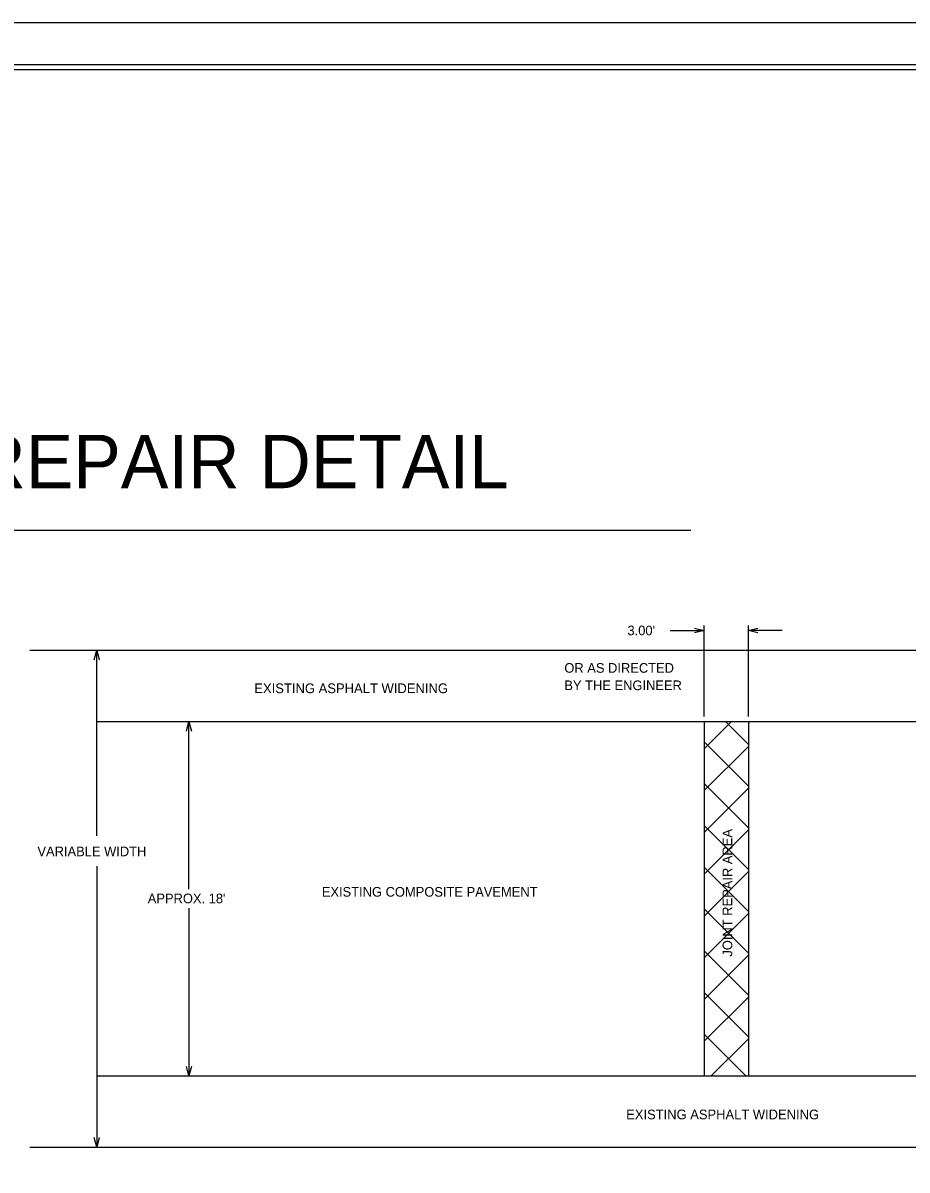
# Model space of a CAD drawing. Extents: x 2455709 to 2456046, y 594728 to 594947.
# Drawn here: x 2455864.9 to 2455949.3, y 594837 to 594946.6 of the extents above; entities that cross this region are included whole.
import ezdxf

# ---------------------------------------------------------------- set-up
doc = ezdxf.new("R2010")
doc.units = 0
for name, color, linetype in [('Default', 7, 'Continuous'), ('Old_Level_3', 7, 'Continuous'), ('Prop Horizontal Alignment', 7, 'Continuous'), ('Prop Roadway Culvert', 7, 'Continuous'), ('Prop Vertical Profile Grade', 7, 'Continuous')]:
    doc.layers.add(name, color=color, linetype=linetype)

msp = doc.modelspace()

# ---------------------------------------------------------------- linework, layer by layer
at = {"layer": 'Default'}
for p, q in [((2455830.77, 594898.13), (2455928.67, 594898.13)), ((2455830.77, 594898.13), (2455928.67, 594898.13)), ((2455929.93, 594880.31), (2455929.93, 594889)), ((2455929.93, 594880.31), (2455929.93, 594889)), ((2455934.16, 594880.31), (2455934.16, 594889)), ((2455934.16, 594880.31), (2455934.16, 594889)), ((2455926.7, 594888.54), (2455929.93, 594888.54)), ((2455926.7, 594888.54), (2455929.93, 594888.54)), ((2455937.39, 594888.54), (2455934.16, 594888.54)), ((2455937.39, 594888.54), (2455934.16, 594888.54)), ((2455865.51, 594886.65), (2455872.36, 594886.65)), ((2455865.51, 594886.65), (2455872.36, 594886.65)), ((2455871.9, 594870.64), (2455871.9, 594886.65)), ((2455871.9, 594868.91), (2455871.9, 594886.65)), ((2455871.9, 594886.65), (2455992.19, 594886.65)), ((2455871.9, 594879.85), (2455992.19, 594879.85)), ((2455871.9, 594879.85), (2455992.19, 594879.85)), ((2455871.9, 594879.85), (2455992.19, 594879.85)), ((2455871.9, 594879.85), (2455992.19, 594879.85)), ((2455871.9, 594879.85), (2455992.19, 594879.85)), ((2455871.9, 594879.85), (2455992.19, 594879.85)), ((2455871.9, 594879.85), (2455992.19, 594879.85)), ((2455871.9, 594879.85), (2455992.19, 594879.85)), ((2455871.9, 594879.85), (2455992.19, 594879.85)), ((2455874.32, 594879.85), (2455881.18, 594879.85)), ((2455874.32, 594879.85), (2455881.18, 594879.85)), ((2455880.72, 594863.84), (2455880.72, 594879.85)), ((2455880.72, 594863.84), (2455880.72, 594879.85)), ((2455929.93, 594879.85), (2455929.93, 594845.98)), ((2455929.93, 594877.23), (2455932.55, 594879.85)), ((2455929.93, 594879.85), (2455934.16, 594879.85)), ((2455929.93, 594879.85), (2455929.93, 594845.98)), ((2455929.93, 594877.23), (2455932.55, 594879.85)), ((2455929.93, 594879.85), (2455934.16, 594879.85)), ((2455931.97, 594879.85), (2455934.16, 594877.66)), ((2455931.97, 594879.85), (2455934.16, 594877.66)), ((2455934.16, 594879.85), (2455934.16, 594845.98)), ((2455934.16, 594879.85), (2455934.16, 594845.98)), ((2455929.93, 594877.91), (2455934.16, 594873.67)), ((2455929.93, 594877.91), (2455934.16, 594873.67)), ((2455929.93, 594873.24), (2455934.16, 594877.47)), ((2455929.93, 594873.24), (2455934.16, 594877.47)), ((2455929.93, 594873.92), (2455934.16, 594869.68)), ((2455929.93, 594873.92), (2455934.16, 594869.68)), ((2455929.93, 594869.25), (2455934.16, 594873.48)), ((2455929.93, 594869.25), (2455934.16, 594873.48)), ((2455929.93, 594869.92), (2455934.16, 594865.69)), ((2455929.93, 594869.92), (2455934.16, 594865.69)), ((2455929.93, 594865.25), (2455934.16, 594869.49)), ((2455929.93, 594865.25), (2455934.16, 594869.49)), ((2455871.9, 594866.01), (2455871.9, 594839.18)), ((2455929.93, 594865.93), (2455934.16, 594861.7)), ((2455929.93, 594865.93), (2455934.16, 594861.7)), ((2455929.93, 594861.26), (2455934.16, 594865.5)), ((2455929.93, 594861.26), (2455934.16, 594865.5)), ((2455871.9, 594862), (2455871.9, 594845.98)), ((2455880.72, 594862), (2455880.72, 594845.98)), ((2455880.72, 594862), (2455880.72, 594845.98)), ((2455929.93, 594861.94), (2455934.16, 594857.71)), ((2455929.93, 594861.94), (2455934.16, 594857.71)), ((2455929.93, 594857.27), (2455934.16, 594861.5)), ((2455929.93, 594857.27), (2455934.16, 594861.5)), ((2455929.93, 594857.95), (2455934.16, 594853.71)), ((2455929.93, 594857.95), (2455934.16, 594853.71)), ((2455929.93, 594853.28), (2455934.16, 594857.51)), ((2455929.93, 594853.28), (2455934.16, 594857.51)), ((2455929.93, 594853.96), (2455934.16, 594849.72)), ((2455929.93, 594853.96), (2455934.16, 594849.72)), ((2455929.93, 594849.29), (2455934.16, 594853.52)), ((2455929.93, 594849.29), (2455934.16, 594853.52)), ((2455929.93, 594849.96), (2455933.91, 594845.98)), ((2455929.93, 594849.96), (2455933.91, 594845.98)), ((2455930.61, 594845.98), (2455934.16, 594849.53)), ((2455930.61, 594845.98), (2455934.16, 594849.53)), ((2455871.9, 594845.98), (2455992.19, 594845.98)), ((2455871.9, 594845.98), (2455992.19, 594845.98)), ((2455874.32, 594845.98), (2455881.18, 594845.98)), ((2455874.32, 594845.98), (2455881.18, 594845.98)), ((2455929.93, 594845.98), (2455934.16, 594845.98)), ((2455929.93, 594845.98), (2455934.16, 594845.98)), ((2455865.51, 594839.18), (2455872.36, 594839.18)), ((2455865.51, 594839.18), (2455872.36, 594839.18)), ((2455871.9, 594839.18), (2455992.19, 594839.18))]:
    msp.add_line(p, q, dxfattribs=at)
for points in [[(2455929.01, 594888.77), (2455929.93, 594888.54), (2455929.01, 594888.31)], [(2455929.01, 594888.77), (2455929.93, 594888.54), (2455929.01, 594888.31)], [(2455935.08, 594888.31), (2455934.16, 594888.54), (2455935.08, 594888.77)], [(2455935.08, 594888.31), (2455934.16, 594888.54), (2455935.08, 594888.77)], [(2455871.67, 594885.73), (2455871.9, 594886.65), (2455872.13, 594885.73)], [(2455871.67, 594885.73), (2455871.9, 594886.65), (2455872.13, 594885.73)], [(2455880.49, 594878.93), (2455880.72, 594879.85), (2455880.95, 594878.93)], [(2455880.49, 594878.93), (2455880.72, 594879.85), (2455880.95, 594878.93)], [(2455880.95, 594846.9), (2455880.72, 594845.98), (2455880.49, 594846.9)], [(2455880.95, 594846.9), (2455880.72, 594845.98), (2455880.49, 594846.9)], [(2455872.13, 594840.1), (2455871.9, 594839.18), (2455871.67, 594840.1)], [(2455872.13, 594840.1), (2455871.9, 594839.18), (2455871.67, 594840.1)]]:
    msp.add_lwpolyline(points, dxfattribs=at)
at = {"layer": 'Prop Horizontal Alignment'}
msp.add_lwpolyline([(2456042.11, 594942.08), (2455742.1, 594942.08), (2455742.1, 594732.08), (2456042.11, 594732.08)], close=True, dxfattribs=at)
at = {"layer": 'Prop Roadway Culvert'}
msp.add_lwpolyline([(2455708.81, 594727.57), (2456045.51, 594727.57), (2456045.51, 594946.57), (2455708.81, 594946.57)], close=True, dxfattribs=at)
at = {"layer": 'Prop Vertical Profile Grade'}
msp.add_lwpolyline([(2455711.41, 594731.57), (2456044.6, 594731.58), (2456044.61, 594942.57), (2455711.41, 594942.57)], close=True, dxfattribs=at)

# ---------------------------------------------------------------- texts
at = {"layer": 'Default'}
for s, height, rotation, p in [("3.00'", 0.922, 360, (2455922.61, 594888.08)), ("3.00'", 0.922, 360, (2455922.61, 594888.08)), ('OR AS DIRECTED', 0.9216, 360, (2455916.58, 594884.5)), ('EXISTING ASPHALT WIDENING', 0.9292, 360, (2455886.96, 594882.55)), ('BY THE ENGINEER', 0.9216, 360, (2455916.58, 594882.84)), ('JOINT REPAIR AREA', 0.9216, 90, (2455932.62, 594857.38)), ('JOINT REPAIR AREA', 0.9216, 90, (2455932.62, 594857.38)), ('VARIABLE WIDTH', 0.9216, 360, (2455866.24, 594866.97)), ('EXISTING COMPOSITE PAVEMENT', 0.9216, 360, (2455893.41, 594863.11)), ("APPROX. 18'", 0.9216, 360, (2455876.78, 594862.48)), ('EXISTING ASPHALT WIDENING', 0.9254, 360, (2455922.49, 594841.84))]:
    msp.add_text(s, height=height, rotation=rotation, dxfattribs=at).set_placement(p)
at = {"layer": 'Old_Level_3'}
msp.add_text('JOINT REPAIR DETAIL', height=5.0897, rotation=0, dxfattribs=at).set_placement((2455838.66, 594902.13))
msp.add_text('JOINT REPAIR DETAIL', height=5.0897, rotation=0, dxfattribs=at).set_placement((2455838.66, 594902.13))

doc.saveas('drawing.dxf')
